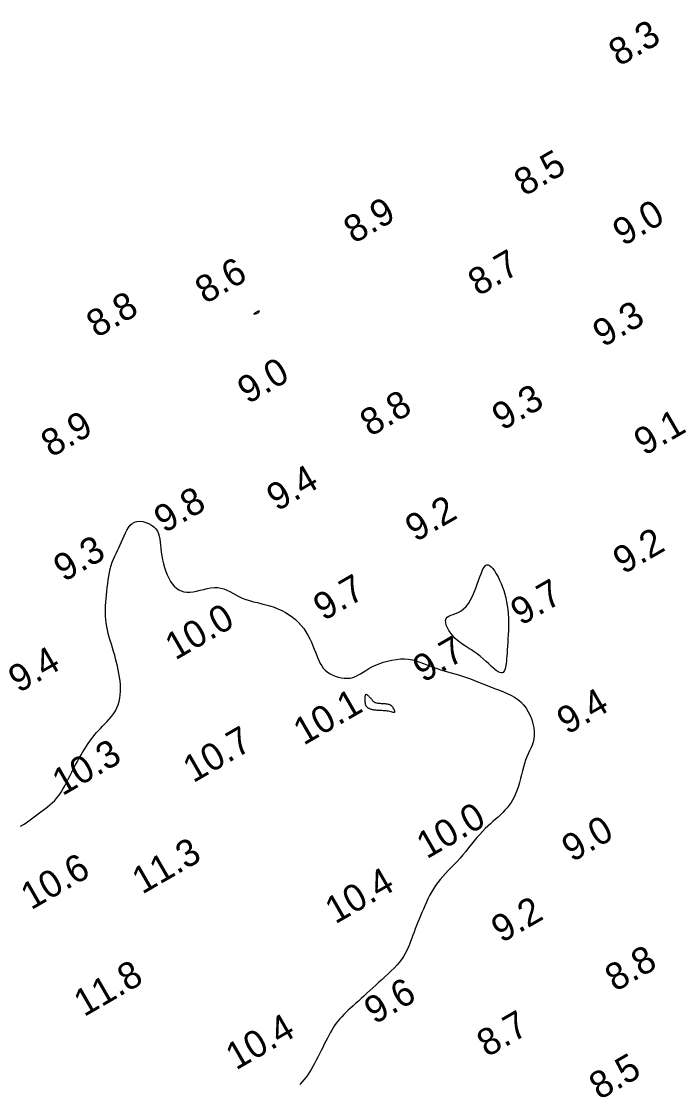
# Model space of a CAD drawing. Extents: x 3024098 to 3056816, y 418252 to 509144.
# Drawn here: x 3033873.5 to 3033993.4, y 418818.5 to 419015.1 of the extents above; entities that cross this region are included whole.
import ezdxf

# ---------------------------------------------------------------- set-up
doc = ezdxf.new("R2010")
doc.units = 0
doc.layers.add('V-CHAN-CONT-EL10', color=7, linetype='Continuous')
doc.layers.add('V-TOPO-SOUN-0911', color=7, linetype='Continuous')

msp = doc.modelspace()

# ---------------------------------------------------------------- linework, layer by layer
at = {"layer": 'V-CHAN-CONT-EL10'}
for points in [[(3033916.46, 418960.96), (3033916.51, 418961.01), (3033916.58, 418961.07), (3033916.68, 418961.13), (3033916.79, 418961.2), (3033916.9, 418961.27), (3033917.01, 418961.33), (3033917.1, 418961.39), (3033917.18, 418961.43), (3033917.23, 418961.47), (3033917.28, 418961.49), (3033917.31, 418961.51), (3033917.33, 418961.52), (3033917.35, 418961.53), (3033917.36, 418961.53), (3033917.36, 418961.54), (3033917.37, 418961.54), (3033917.38, 418961.54), (3033917.39, 418961.54), (3033917.4, 418961.54), (3033917.4, 418961.54), (3033917.41, 418961.54), (3033917.42, 418961.54), (3033917.42, 418961.54), (3033917.43, 418961.53), (3033917.43, 418961.53), (3033917.44, 418961.52), (3033917.44, 418961.51), (3033917.44, 418961.5), (3033917.44, 418961.48), (3033917.44, 418961.46), (3033917.43, 418961.43), (3033917.43, 418961.4), (3033917.42, 418961.36), (3033917.41, 418961.32), (3033917.39, 418961.28), (3033917.35, 418961.23), (3033917.31, 418961.18), (3033917.24, 418961.13), (3033917.16, 418961.08), (3033917.06, 418961.04), (3033916.95, 418960.99), (3033916.83, 418960.96), (3033916.71, 418960.93), (3033916.61, 418960.91), (3033916.52, 418960.9), (3033916.47, 418960.9), (3033916.44, 418960.92)], [(3033957.26, 418898.46), (3033956.71, 418898.82), (3033956.17, 418899.16), (3033955.64, 418899.48), (3033955.12, 418899.81), (3033954.63, 418900.15), (3033954.15, 418900.52), (3033953.7, 418900.93), (3033953.27, 418901.39), (3033952.89, 418901.88), (3033952.56, 418902.39), (3033952.28, 418902.91), (3033952.08, 418903.4), (3033951.97, 418903.86), (3033951.95, 418904.27), (3033952.03, 418904.61), (3033952.23, 418904.87), (3033952.52, 418905.06), (3033952.9, 418905.23), (3033953.33, 418905.38), (3033953.8, 418905.54), (3033954.3, 418905.75), (3033954.8, 418906.02), (3033955.28, 418906.39), (3033955.74, 418906.86), (3033956.16, 418907.42), (3033956.54, 418908.06), (3033956.9, 418908.76), (3033957.23, 418909.48), (3033957.54, 418910.22), (3033957.81, 418910.95), (3033958.06, 418911.65), (3033958.29, 418912.3), (3033958.51, 418912.9), (3033958.71, 418913.42), (3033958.92, 418913.85), (3033959.12, 418914.2), (3033959.33, 418914.44), (3033959.56, 418914.57), (3033959.81, 418914.57), (3033960.08, 418914.44), (3033960.38, 418914.2), (3033960.69, 418913.85), (3033961, 418913.41), (3033961.32, 418912.9), (3033961.64, 418912.33), (3033961.94, 418911.72), (3033962.22, 418911.08), (3033962.47, 418910.44), (3033962.7, 418909.78), (3033962.9, 418909.1), (3033963.08, 418908.42), (3033963.23, 418907.72), (3033963.35, 418907), (3033963.45, 418906.27), (3033963.51, 418905.51), (3033963.56, 418904.74), (3033963.57, 418903.96), (3033963.57, 418903.17), (3033963.55, 418902.39), (3033963.52, 418901.62), (3033963.48, 418900.87), (3033963.44, 418900.15), (3033963.4, 418899.48), (3033963.35, 418898.84), (3033963.31, 418898.25), (3033963.27, 418897.71), (3033963.23, 418897.21), (3033963.19, 418896.75), (3033963.14, 418896.33), (3033963.08, 418895.94), (3033963.02, 418895.6), (3033962.94, 418895.29), (3033962.85, 418895.02), (3033962.73, 418894.8), (3033962.59, 418894.64), (3033962.42, 418894.55), (3033962.21, 418894.54), (3033961.95, 418894.6), (3033961.65, 418894.77), (3033961.29, 418895.02), (3033960.88, 418895.36), (3033960.43, 418895.76), (3033959.95, 418896.21), (3033959.44, 418896.68), (3033958.91, 418897.16), (3033958.37, 418897.63), (3033957.81, 418898.07)], [(3033938.26, 418887.84), (3033938.39, 418887.8), (3033938.54, 418887.77), (3033938.69, 418887.75), (3033938.86, 418887.72), (3033939.04, 418887.7), (3033939.23, 418887.68), (3033939.44, 418887.67), (3033939.67, 418887.65), (3033939.91, 418887.64), (3033940.16, 418887.63), (3033940.41, 418887.62), (3033940.67, 418887.6), (3033940.93, 418887.58), (3033941.17, 418887.55), (3033941.41, 418887.52), (3033941.63, 418887.47), (3033941.84, 418887.42), (3033942.02, 418887.36), (3033942.19, 418887.32), (3033942.33, 418887.29), (3033942.44, 418887.28), (3033942.52, 418887.29), (3033942.57, 418887.33), (3033942.58, 418887.4), (3033942.57, 418887.51), (3033942.52, 418887.63), (3033942.46, 418887.77), (3033942.37, 418887.92), (3033942.27, 418888.07), (3033942.16, 418888.21), (3033942.04, 418888.34), (3033941.92, 418888.45), (3033941.79, 418888.54), (3033941.66, 418888.62), (3033941.52, 418888.68), (3033941.36, 418888.72), (3033941.2, 418888.76), (3033941.01, 418888.79), (3033940.81, 418888.81), (3033940.59, 418888.83), (3033940.36, 418888.84), (3033940.12, 418888.85), (3033939.88, 418888.87), (3033939.65, 418888.89), (3033939.42, 418888.91), (3033939.22, 418888.95), (3033939.04, 418888.99), (3033938.89, 418889.04), (3033938.77, 418889.11), (3033938.66, 418889.19), (3033938.57, 418889.27), (3033938.49, 418889.36), (3033938.42, 418889.47), (3033938.34, 418889.57), (3033938.26, 418889.68), (3033938.17, 418889.8), (3033938.06, 418889.91), (3033937.96, 418890.02), (3033937.84, 418890.13), (3033937.73, 418890.23), (3033937.63, 418890.33), (3033937.52, 418890.41), (3033937.43, 418890.47), (3033937.35, 418890.52), (3033937.28, 418890.55), (3033937.22, 418890.56), (3033937.17, 418890.55), (3033937.13, 418890.52), (3033937.1, 418890.47), (3033937.07, 418890.39), (3033937.05, 418890.29), (3033937.03, 418890.17), (3033937.02, 418890.03), (3033937.01, 418889.87), (3033937.01, 418889.7), (3033937.02, 418889.53), (3033937.02, 418889.36), (3033937.03, 418889.19), (3033937.05, 418889.04), (3033937.07, 418888.9), (3033937.09, 418888.78), (3033937.12, 418888.67), (3033937.15, 418888.57), (3033937.19, 418888.48), (3033937.24, 418888.4), (3033937.3, 418888.33), (3033937.36, 418888.27), (3033937.43, 418888.2), (3033937.51, 418888.15), (3033937.59, 418888.09), (3033937.69, 418888.04), (3033937.79, 418888), (3033937.9, 418887.95), (3033938.01, 418887.91), (3033938.13, 418887.87)]]:
    msp.add_lwpolyline(points, close=True, dxfattribs=at)
msp.add_lwpolyline([(3033873.33, 418866.18), (3033873.86, 418866.49), (3033874.37, 418866.83), (3033874.87, 418867.18), (3033875.36, 418867.55), (3033875.84, 418867.92), (3033876.33, 418868.29), (3033876.82, 418868.65), (3033877.31, 418869.01), (3033877.8, 418869.37), (3033878.28, 418869.74), (3033878.76, 418870.13), (3033879.21, 418870.53), (3033879.66, 418870.97), (3033880.07, 418871.44), (3033880.46, 418871.95), (3033880.83, 418872.49), (3033881.18, 418873.07), (3033881.52, 418873.67), (3033881.85, 418874.29), (3033882.17, 418874.92), (3033882.49, 418875.57), (3033882.82, 418876.22), (3033883.16, 418876.87), (3033883.5, 418877.52), (3033883.85, 418878.15), (3033884.19, 418878.77), (3033884.54, 418879.38), (3033884.88, 418879.95), (3033885.21, 418880.5), (3033885.54, 418881.01), (3033885.85, 418881.49), (3033886.15, 418881.93), (3033886.45, 418882.35), (3033886.76, 418882.75), (3033887.07, 418883.13), (3033887.4, 418883.52), (3033887.74, 418883.9), (3033888.11, 418884.29), (3033888.51, 418884.7), (3033888.92, 418885.12), (3033889.34, 418885.56), (3033889.76, 418886.02), (3033890.16, 418886.5), (3033890.54, 418887), (3033890.88, 418887.53), (3033891.17, 418888.07), (3033891.4, 418888.64), (3033891.58, 418889.24), (3033891.71, 418889.85), (3033891.79, 418890.48), (3033891.83, 418891.12), (3033891.83, 418891.77), (3033891.8, 418892.43), (3033891.74, 418893.1), (3033891.65, 418893.77), (3033891.54, 418894.44), (3033891.42, 418895.11), (3033891.27, 418895.79), (3033891.11, 418896.46), (3033890.93, 418897.14), (3033890.75, 418897.82), (3033890.55, 418898.49), (3033890.35, 418899.17), (3033890.14, 418899.84), (3033889.94, 418900.52), (3033889.74, 418901.18), (3033889.56, 418901.85), (3033889.4, 418902.51), (3033889.27, 418903.16), (3033889.17, 418903.8), (3033889.09, 418904.44), (3033889.06, 418905.07), (3033889.04, 418905.7), (3033889.05, 418906.33), (3033889.08, 418906.97), (3033889.13, 418907.61), (3033889.19, 418908.27), (3033889.25, 418908.94), (3033889.31, 418909.63), (3033889.39, 418910.34), (3033889.47, 418911.04), (3033889.56, 418911.75), (3033889.67, 418912.44), (3033889.79, 418913.12), (3033889.94, 418913.78), (3033890.11, 418914.42), (3033890.31, 418915.01), (3033890.52, 418915.58), (3033890.76, 418916.13), (3033891.01, 418916.66), (3033891.27, 418917.18), (3033891.53, 418917.71), (3033891.78, 418918.24), (3033892.03, 418918.78), (3033892.27, 418919.34), (3033892.51, 418919.91), (3033892.75, 418920.46), (3033893.01, 418920.98), (3033893.29, 418921.46), (3033893.61, 418921.87), (3033893.98, 418922.2), (3033894.4, 418922.44), (3033894.87, 418922.58), (3033895.4, 418922.6), (3033895.94, 418922.54), (3033896.49, 418922.4), (3033897.03, 418922.18), (3033897.53, 418921.9), (3033897.98, 418921.56), (3033898.35, 418921.18), (3033898.64, 418920.76), (3033898.84, 418920.31), (3033898.99, 418919.83), (3033899.09, 418919.31), (3033899.15, 418918.75), (3033899.21, 418918.16), (3033899.27, 418917.54), (3033899.34, 418916.88), (3033899.45, 418916.19), (3033899.59, 418915.48), (3033899.76, 418914.76), (3033899.96, 418914.04), (3033900.19, 418913.34), (3033900.46, 418912.68), (3033900.74, 418912.06), (3033901.06, 418911.49), (3033901.4, 418911), (3033901.77, 418910.57), (3033902.17, 418910.22), (3033902.6, 418909.93), (3033903.06, 418909.72), (3033903.56, 418909.58), (3033904.09, 418909.51), (3033904.65, 418909.51), (3033905.26, 418909.58), (3033905.89, 418909.7), (3033906.54, 418909.85), (3033907.21, 418910.01), (3033907.88, 418910.16), (3033908.54, 418910.28), (3033909.18, 418910.35), (3033909.8, 418910.34), (3033910.38, 418910.25), (3033910.94, 418910.09), (3033911.49, 418909.86), (3033912.03, 418909.59), (3033912.58, 418909.29), (3033913.14, 418908.98), (3033913.73, 418908.68), (3033914.35, 418908.4), (3033915.01, 418908.15), (3033915.71, 418907.93), (3033916.44, 418907.73), (3033917.18, 418907.55), (3033917.94, 418907.36), (3033918.71, 418907.16), (3033919.47, 418906.94), (3033920.22, 418906.69), (3033920.95, 418906.41), (3033921.66, 418906.08), (3033922.34, 418905.72), (3033923, 418905.32), (3033923.62, 418904.88), (3033924.2, 418904.41), (3033924.75, 418903.89), (3033925.25, 418903.34), (3033925.7, 418902.76), (3033926.12, 418902.14), (3033926.49, 418901.51), (3033926.83, 418900.87), (3033927.14, 418900.22), (3033927.42, 418899.58), (3033927.67, 418898.96), (3033927.9, 418898.36), (3033928.12, 418897.79), (3033928.34, 418897.26), (3033928.55, 418896.75), (3033928.78, 418896.28), (3033929.04, 418895.85), (3033929.32, 418895.45), (3033929.65, 418895.08), (3033930.04, 418894.74), (3033930.48, 418894.43), (3033930.98, 418894.17), (3033931.51, 418893.94), (3033932.07, 418893.77), (3033932.64, 418893.64), (3033933.21, 418893.57), (3033933.77, 418893.56), (3033934.31, 418893.61), (3033934.81, 418893.73), (3033935.28, 418893.91), (3033935.74, 418894.14), (3033936.2, 418894.41), (3033936.68, 418894.7), (3033937.18, 418895.02), (3033937.72, 418895.34), (3033938.32, 418895.66), (3033938.97, 418895.97), (3033939.68, 418896.26), (3033940.43, 418896.52), (3033941.21, 418896.74), (3033942, 418896.93), (3033942.81, 418897.06), (3033943.6, 418897.13), (3033944.37, 418897.14), (3033945.11, 418897.07), (3033945.83, 418896.95), (3033946.52, 418896.77), (3033947.19, 418896.55), (3033947.85, 418896.31), (3033948.49, 418896.06), (3033949.13, 418895.8), (3033949.76, 418895.56), (3033950.39, 418895.34), (3033951.03, 418895.14), (3033951.67, 418894.95), (3033952.32, 418894.77), (3033952.98, 418894.58), (3033953.65, 418894.39), (3033954.35, 418894.18), (3033955.05, 418893.96), (3033955.79, 418893.71), (3033956.53, 418893.43), (3033957.29, 418893.15), (3033958.06, 418892.84), (3033958.84, 418892.54), (3033959.61, 418892.22), (3033960.38, 418891.92), (3033961.15, 418891.61), (3033961.9, 418891.33), (3033962.63, 418891.03), (3033963.34, 418890.73), (3033964.02, 418890.41), (3033964.67, 418890.05), (3033965.28, 418889.65), (3033965.84, 418889.19), (3033966.36, 418888.65), (3033966.83, 418888.05), (3033967.23, 418887.37), (3033967.58, 418886.66), (3033967.87, 418885.91), (3033968.09, 418885.15), (3033968.24, 418884.4), (3033968.32, 418883.67), (3033968.33, 418882.98), (3033968.26, 418882.34), (3033968.13, 418881.75), (3033967.95, 418881.19), (3033967.73, 418880.65), (3033967.48, 418880.12), (3033967.23, 418879.58), (3033966.98, 418879.02), (3033966.74, 418878.42), (3033966.52, 418877.79), (3033966.33, 418877.11), (3033966.15, 418876.42), (3033965.98, 418875.7), (3033965.81, 418874.99), (3033965.62, 418874.27), (3033965.43, 418873.58), (3033965.21, 418872.91), (3033964.96, 418872.28), (3033964.68, 418871.68), (3033964.38, 418871.11), (3033964.05, 418870.57), (3033963.69, 418870.07), (3033963.32, 418869.59), (3033962.93, 418869.13), (3033962.51, 418868.7), (3033962.08, 418868.28), (3033961.64, 418867.88), (3033961.18, 418867.48), (3033960.71, 418867.07), (3033960.23, 418866.65), (3033959.74, 418866.21), (3033959.25, 418865.74), (3033958.75, 418865.23), (3033958.25, 418864.68), (3033957.74, 418864.09), (3033957.23, 418863.47), (3033956.72, 418862.84), (3033956.2, 418862.19), (3033955.68, 418861.54), (3033955.15, 418860.9), (3033954.62, 418860.28), (3033954.07, 418859.68), (3033953.53, 418859.1), (3033952.99, 418858.54), (3033952.45, 418857.99), (3033951.93, 418857.45), (3033951.43, 418856.9), (3033950.95, 418856.35), (3033950.5, 418855.78), (3033950.08, 418855.2), (3033949.7, 418854.6), (3033949.34, 418853.99), (3033949, 418853.37), (3033948.69, 418852.75), (3033948.39, 418852.12), (3033948.11, 418851.49), (3033947.83, 418850.86), (3033947.57, 418850.24), (3033947.31, 418849.62), (3033947.05, 418849.01), (3033946.81, 418848.41), (3033946.57, 418847.81), (3033946.33, 418847.21), (3033946.11, 418846.62), (3033945.89, 418846.04), (3033945.68, 418845.46), (3033945.47, 418844.88), (3033945.25, 418844.31), (3033945.02, 418843.75), (3033944.77, 418843.19), (3033944.48, 418842.63), (3033944.16, 418842.09), (3033943.8, 418841.54), (3033943.38, 418841), (3033942.92, 418840.47), (3033942.43, 418839.94), (3033941.9, 418839.41), (3033941.35, 418838.89), (3033940.78, 418838.37), (3033940.2, 418837.85), (3033939.63, 418837.33), (3033939.05, 418836.81), (3033938.48, 418836.29), (3033937.93, 418835.78), (3033937.38, 418835.28), (3033936.84, 418834.78), (3033936.32, 418834.3), (3033935.81, 418833.83), (3033935.31, 418833.38), (3033934.83, 418832.95), (3033934.37, 418832.53), (3033933.93, 418832.13), (3033933.51, 418831.73), (3033933.11, 418831.34), (3033932.73, 418830.95), (3033932.37, 418830.55), (3033932.04, 418830.15), (3033931.72, 418829.74), (3033931.43, 418829.32), (3033931.15, 418828.88), (3033930.88, 418828.43), (3033930.61, 418827.96), (3033930.35, 418827.47), (3033930.08, 418826.96), (3033929.81, 418826.42), (3033929.52, 418825.86), (3033929.23, 418825.28), (3033928.93, 418824.68), (3033928.62, 418824.08), (3033928.3, 418823.48), (3033927.99, 418822.88), (3033927.68, 418822.3), (3033927.37, 418821.73), (3033927.06, 418821.19), (3033926.75, 418820.68), (3033926.44, 418820.18), (3033926.11, 418819.71), (3033925.76, 418819.26), (3033925.38, 418818.83), (3033924.96, 418818.41)], dxfattribs=at)

# ---------------------------------------------------------------- texts
at = {"layer": 'V-TOPO-SOUN-0911'}
for s, p in [('8.3', (3033984.01, 419006.66)), ('8.5', (3033966.51, 418982.63)), ('8.9', (3033934.99, 418973.87)), ('9.0', (3033984.76, 418973.41)), ('8.7', (3033957.99, 418964.15)), ('8.6', (3033907.53, 418962.72)), ('8.8', (3033887.42, 418956.44)), ('9.3', (3033981.06, 418954.71)), ('9.0', (3033915.36, 418944.2)), ('8.8', (3033938.01, 418938.17)), ('9.3', (3033962.42, 418939.29)), ('8.9', (3033879.02, 418934.33)), ('9.1', (3033988.68, 418934.64)), ('9.4', (3033920.75, 418924.36)), ('9.8', (3033899.92, 418920.32)), ('9.2', (3033946.38, 418918.68)), ('9.2', (3033984.8, 418912.71)), ('9.3', (3033881.35, 418911.3)), ('9.7', (3033929.38, 418904.08)), ('9.7', (3033965.87, 418903.2)), ('10.0 ', (3033901.97, 418896.82)), ('9.7', (3033947.82, 418892.66)), ('9.4', (3033872.99, 418890.76)), ('9.4', (3033974.43, 418883.05)), ('10.1 ', (3033925.69, 418881.06)), ('10.7 ', (3033905.27, 418874.12)), ('10.3 ', (3033881.09, 418871.73)), ('10.0 ', (3033948.46, 418860.04)), ('9.0', (3033975.33, 418859.46)), ('11.3 ', (3033895.85, 418853.52)), ('10.6 ', (3033875.28, 418850.6)), ('10.4 ', (3033931.55, 418848.01)), ('9.2', (3033962.29, 418844.5)), ('8.8', (3033983.32, 418835.48)), ('11.8 ', (3033885.09, 418830.85)), ('9.6', (3033938.8, 418829.45)), ('10.4 ', (3033913.18, 418820.97)), ('8.7', (3033959.63, 418823.37)), ('8.5', (3033980.39, 418815.47))]:
    msp.add_text(s, height=5, rotation=30, dxfattribs=at).set_placement(p)

doc.saveas('drawing.dxf')
